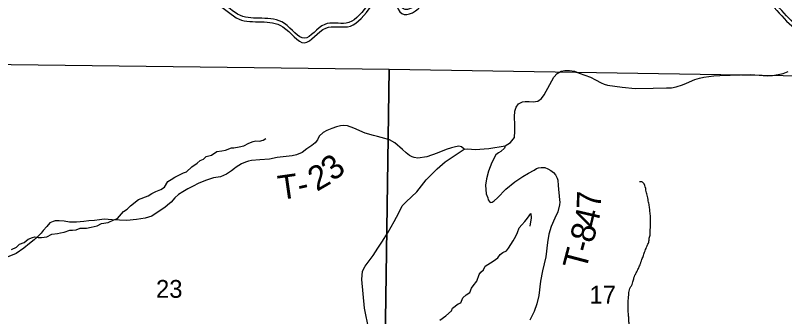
# Model space of a CAD drawing. Extents: x 0 to 191, y 0 to 55.
# Drawn here: x 147.556 to 148.459, y 21.192 to 21.545 of the extents above; entities that cross this region are included whole.
import ezdxf

# ---------------------------------------------------------------- set-up
doc = ezdxf.new("R2010")
doc.units = 0
for name, color, linetype in [('GM_X_Corporation', 7, 'Continuous'), ('GM_X_Minor_River', 7, 'Continuous'), ('GM_X_Section_Text', 7, 'Continuous'), ('GM_X_State_Route', 7, 'Continuous'), ('GM_X_Township_Road', 7, 'Continuous'), ('GM_X_Township_Road_Text', 7, 'Continuous')]:
    doc.layers.add(name, color=color, linetype=linetype)

msp = doc.modelspace()

# ---------------------------------------------------------------- linework, layer by layer
at = {"layer": 'GM_X_Corporation'}
for points in [[(147.48759, 21.48829), (147.99507, 21.48227), (147.98775, 20.97285), (147.48091, 20.97812)], [(147.99507, 21.48227), (148.5062, 21.47402), (148.49568, 20.96286), (147.98775, 20.97285)]]:
    msp.add_lwpolyline(points, close=True, dxfattribs=at)
at = {"layer": 'GM_X_Minor_River'}
for points in [[(147.55182, 21.27039), (147.55784, 21.27295), (147.56139, 21.27642), (147.56665, 21.27858), (147.57133, 21.28264), (147.57641, 21.28442), (147.57924, 21.28503), (147.58322, 21.28452), (147.58719, 21.28457), (147.59324, 21.28523), (147.59944, 21.28817), (147.60605, 21.28921), (147.60945, 21.28983), (147.61379, 21.29084), (147.62019, 21.29302), (147.62341, 21.29288), (147.62775, 21.29332), (147.63264, 21.29529), (147.64002, 21.29559), (147.64549, 21.29661), (147.65229, 21.29804), (147.65754, 21.30096), (147.66528, 21.30222), (147.67205, 21.30516), (147.67638, 21.30693), (147.68326, 21.31482), (147.68777, 21.31755), (147.69149, 21.32159), (147.70103, 21.32913), (147.71214, 21.33328), (147.71664, 21.33601), (147.72134, 21.33835), (147.72736, 21.34091), (147.73148, 21.34344), (147.73536, 21.35014), (147.7393, 21.35248), (147.7438, 21.3552), (147.75376, 21.36029), (147.75715, 21.36147), (147.76349, 21.36745), (147.76986, 21.37172), (147.77341, 21.37501), (147.77736, 21.37658), (147.78054, 21.37948), (147.78657, 21.38108), (147.79275, 21.38535), (147.79898, 21.38639), (147.80314, 21.38702), (147.8101, 21.38959), (147.81294, 21.38963), (147.81898, 21.39085), (147.82463, 21.39226), (147.83045, 21.39538), (147.83573, 21.39717), (147.83874, 21.39797), (147.8431, 21.39765), (147.84725, 21.39866), (147.85044, 21.40061)], [(148.05471, 21.18746), (148.06164, 21.19249), (148.06836, 21.19829), (148.06945, 21.20134), (148.07619, 21.20638), (148.07939, 21.20775), (148.08157, 21.21368), (148.0855, 21.21696), (148.08981, 21.21987), (148.092, 21.22503), (148.09386, 21.22772), (148.09794, 21.2331), (148.10105, 21.24093), (148.10271, 21.2438), (148.10588, 21.24651), (148.10809, 21.25091), (148.11728, 21.25674), (148.12271, 21.26062), (148.12549, 21.26446), (148.12867, 21.26697), (148.13299, 21.26893), (148.13541, 21.27182), (148.138, 21.27603), (148.14078, 21.28044), (148.14372, 21.28618), (148.14574, 21.29039), (148.14793, 21.29574), (148.15091, 21.29921), (148.15445, 21.30324), (148.15761, 21.30709), (148.15965, 21.30978), (148.1615, 21.31246), (148.16176, 21.30772), (148.16039, 21.29782)]]:
    msp.add_lwpolyline(points, dxfattribs=at)
for points in [[(147.57106, 21.67041), (147.59351, 21.65617), (147.61917, 21.64989), (147.64452, 21.63355), (147.66965, 21.62233), (147.69556, 21.60713), (147.72092, 21.58964), (147.74741, 21.57292), (147.77115, 21.59853), (147.76791, 21.57325), (147.79344, 21.55805), (147.81899, 21.54094), (147.84519, 21.5377), (147.87047, 21.5318), (147.89584, 21.51317), (147.92096, 21.53043), (147.94618, 21.53193), (147.97166, 21.55279), (147.99657, 21.5727), (148.01002, 21.54735), (148.03518, 21.5591), (148.05037, 21.58483), (148.07608, 21.59905), (148.10468, 21.60664), (148.13042, 21.61574), (148.15673, 21.62483), (148.18248, 21.63412), (148.20746, 21.64283), (148.23281, 21.65438), (148.25831, 21.64316), (148.28353, 21.6456), (148.30881, 21.63951), (148.33389, 21.63492), (148.35665, 21.60982), (148.38199, 21.59518), (148.40764, 21.59042), (148.43282, 21.57084), (148.45596, 21.5446), (148.48115, 21.52464), (148.50622, 21.52101), (148.5313, 21.51605), (148.55159, 21.49093), (148.57226, 21.46601), (148.59027, 21.44069), (148.61537, 21.43345), (148.64058, 21.40969), (148.66611, 21.39486), (148.69115, 21.39598), (148.71646, 21.38532), (148.73751, 21.36021), (148.76281, 21.35031), (148.78815, 21.33624), (148.81347, 21.3235), (148.8386, 21.31208), (148.86427, 21.30466), (148.89012, 21.29818), (148.91559, 21.29094), (148.94066, 21.28807), (148.96647, 21.28748), (148.99169, 21.28936), (149.01687, 21.29882), (149.04205, 21.30677), (149.06693, 21.31374)], [(147.57106, 21.67041), (147.59351, 21.65617), (147.61917, 21.64989), (147.64452, 21.63355), (147.66965, 21.62233), (147.69556, 21.60713), (147.72092, 21.58964), (147.74741, 21.57292), (147.77115, 21.59853), (147.76791, 21.57325), (147.79344, 21.55805), (147.81899, 21.54094), (147.84519, 21.5377), (147.87047, 21.5318), (147.89584, 21.51317), (147.92096, 21.53043), (147.94618, 21.53193), (147.97166, 21.55279), (147.99657, 21.5727), (148.01002, 21.54735), (148.03518, 21.5591), (148.05037, 21.58483), (148.07608, 21.59905), (148.10468, 21.60664), (148.13042, 21.61574), (148.15673, 21.62483), (148.18248, 21.63412), (148.20746, 21.64283), (148.23281, 21.65438), (148.25831, 21.64316), (148.28353, 21.6456), (148.30881, 21.63951), (148.33389, 21.63492), (148.35665, 21.60982), (148.38199, 21.59518), (148.40764, 21.59042), (148.43282, 21.57084), (148.45596, 21.5446), (148.48115, 21.52464), (148.50622, 21.52101), (148.5313, 21.51605), (148.55159, 21.49093), (148.57226, 21.46601), (148.59027, 21.44069), (148.61537, 21.43345), (148.64058, 21.40969), (148.66611, 21.39486), (148.69115, 21.39598), (148.71646, 21.38532), (148.73751, 21.36021), (148.76281, 21.35031), (148.78815, 21.33624), (148.81347, 21.3235), (148.8386, 21.31208), (148.86427, 21.30466), (148.89012, 21.29818), (148.91559, 21.29094), (148.94066, 21.28807), (148.96647, 21.28748), (148.99169, 21.28936), (149.01687, 21.29882), (149.04205, 21.30677), (149.06705, 21.31377)], [(149.05968, 21.31692), (149.04083, 21.31085), (149.01547, 21.30285), (148.99077, 21.29356), (148.96636, 21.29174), (148.94095, 21.29233), (148.91642, 21.29514), (148.89122, 21.3023), (148.86538, 21.30877), (148.84008, 21.31609), (148.81531, 21.32734), (148.79014, 21.34001), (148.76463, 21.35418), (148.74007, 21.36378), (148.71906, 21.38885), (148.69192, 21.40028), (148.66717, 21.39917), (148.64314, 21.41313), (148.61754, 21.43726), (148.59288, 21.44437), (148.57564, 21.46861), (148.55489, 21.49363), (148.53364, 21.51993), (148.50694, 21.52521), (148.48289, 21.52869), (148.45891, 21.5477), (148.43575, 21.57396), (148.40943, 21.59442), (148.38348, 21.59924), (148.35936, 21.61318), (148.33608, 21.63886), (148.3097, 21.64368), (148.28383, 21.64991), (148.25901, 21.64751), (148.23278, 21.65905), (148.20587, 21.64678), (148.18105, 21.63813), (148.15531, 21.62885), (148.12901, 21.61976), (148.10342, 21.61072), (148.07448, 21.60303), (148.04729, 21.588), (148.03218, 21.5624), (148.01189, 21.55293), (147.99792, 21.57924), (147.96898, 21.5561), (147.94455, 21.5361), (147.91952, 21.53461), (147.89592, 21.5184), (147.87229, 21.53575), (147.84594, 21.5419), (147.82052, 21.54505), (147.79572, 21.56165), (147.77249, 21.57548), (147.77706, 21.61118), (147.7467, 21.57842), (147.72327, 21.5932), (147.69785, 21.61072), (147.6716, 21.62612), (147.64656, 21.6373), (147.62088, 21.65386), (147.5952, 21.66014), (147.57469, 21.67316)], [(148.29508, 21.26731), (148.29732, 21.27302), (148.299, 21.27664), (148.29994, 21.27892), (148.30048, 21.28348), (148.30122, 21.28596), (148.30157, 21.29014), (148.30173, 21.29374), (148.30189, 21.29792), (148.30204, 21.30343), (148.30181, 21.31026), (148.30119, 21.31633), (148.30059, 21.32183), (148.29941, 21.32752), (148.29803, 21.33435), (148.29726, 21.33681), (148.29666, 21.34022), (148.29434, 21.34742), (148.29166, 21.34987), (148.2892, 21.34967)], [(148.24976, 20.86339), (148.25479, 20.86869), (148.25667, 20.87098), (148.25873, 20.87537), (148.26286, 20.88128), (148.26512, 20.88395), (148.26757, 20.8872), (148.2685, 20.88948), (148.27057, 20.89215), (148.27281, 20.89635), (148.27469, 20.89997), (148.27751, 20.90359), (148.27919, 20.90683), (148.2839, 20.91256), (148.2888, 20.91677), (148.29201, 20.91964), (148.29539, 20.92365), (148.29973, 20.92824), (148.30329, 20.93396), (148.30648, 20.9393), (148.30835, 20.9433), (148.31021, 20.94862), (148.31152, 20.9511), (148.31207, 20.95338), (148.31319, 20.95738), (148.31393, 20.95985), (148.31597, 20.96556), (148.31709, 20.96899), (148.31838, 20.97374), (148.3193, 20.97774), (148.31986, 20.98002), (148.31984, 20.98249), (148.3202, 20.98553), (148.32056, 20.98819), (148.32129, 20.99218), (148.32203, 20.99484), (148.32258, 20.99731), (148.3235, 21.00131), (148.32443, 21.00511), (148.32574, 21.0074), (148.32591, 21.00987), (148.32551, 21.0129), (148.32473, 21.01651), (148.32279, 21.02276), (148.32105, 21.02712), (148.31798, 21.03127), (148.31644, 21.03525), (148.31432, 21.03998), (148.31238, 21.04529), (148.30987, 21.05153), (148.30775, 21.05684), (148.30562, 21.06309), (148.30386, 21.0701), (148.30153, 21.07749), (148.29998, 21.08185), (148.29883, 21.08431), (148.29651, 21.08942), (148.29574, 21.09207), (148.29457, 21.09643), (148.29321, 21.10022), (148.29205, 21.10325), (148.2907, 21.10723), (148.28914, 21.11253), (148.28875, 21.115), (148.28758, 21.11898), (148.28622, 21.12315), (148.28562, 21.1277), (148.28483, 21.13206), (148.28424, 21.13547), (148.28365, 21.13813), (148.28227, 21.14552), (148.28149, 21.14856), (148.2803, 21.15614), (148.27971, 21.15937), (148.27852, 21.16676), (148.27812, 21.16961), (148.27732, 21.17606), (148.27711, 21.17834), (148.27688, 21.18327), (148.27668, 21.18555), (148.27666, 21.18783), (148.27625, 21.192), (148.27611, 21.21288), (148.27628, 21.21535), (148.27663, 21.21972), (148.27848, 21.226), (148.28055, 21.22943), (148.28129, 21.23247), (148.28258, 21.23704), (148.2837, 21.24008), (148.28576, 21.24409), (148.28726, 21.24694), (148.28913, 21.25113), (148.29025, 21.2538), (148.29136, 21.25722), (148.29341, 21.26217), (148.29508, 21.26731)]]:
    msp.add_spline(points, degree=3, dxfattribs=at)
at = {"layer": 'GM_X_State_Route'}
msp.add_lwpolyline([(147.97118, 21.17648), (147.96645, 21.20164), (147.9631, 21.2352), (147.96401, 21.2448), (147.96691, 21.2509), (147.97636, 21.26326), (147.98201, 21.2718), (147.98658, 21.27881), (147.99404, 21.29058), (148.00107, 21.30342), (148.00661, 21.3133), (148.01067, 21.32163), (148.01499, 21.32623), (148.02756, 21.33819), (148.03863, 21.35212), (148.05164, 21.36515), (148.06083, 21.37327), (148.08335, 21.38837), (148.08766, 21.38859), (148.09612, 21.38796), (148.11215, 21.38915), (148.13147, 21.392), (148.13771, 21.39601), (148.1422, 21.40198), (148.14272, 21.40933), (148.14265, 21.41656), (148.14238, 21.42628), (148.14287, 21.43288), (148.14413, 21.43767), (148.14684, 21.44131), (148.15173, 21.44358), (148.15484, 21.44411), (148.15946, 21.44405), (148.1644, 21.44368), (148.16956, 21.44437), (148.17391, 21.44754), (148.17706, 21.45212), (148.18372, 21.464), (148.18853, 21.47262), (148.19227, 21.47708), (148.19717, 21.47959), (148.20149, 21.48041), (148.20672, 21.48068), (148.21295, 21.47982), (148.21828, 21.47761), (148.23153, 21.47262), (148.23737, 21.46977), (148.2442, 21.46607), (148.24766, 21.46465), (148.25133, 21.4634), (148.26867, 21.46087), (148.28414, 21.45953), (148.30502, 21.45999), (148.32094, 21.46004), (148.32661, 21.46018), (148.33209, 21.46121), (148.33956, 21.46369), (148.34433, 21.46583), (148.35403, 21.47011), (148.35956, 21.47159), (148.36452, 21.47262), (148.37636, 21.47413), (148.38326, 21.47465), (148.41978, 21.47579), (148.4389, 21.47445), (148.44523, 21.47461), (148.4519, 21.47579), (148.45775, 21.47702), (148.46352, 21.47935)], dxfattribs=at)
at = {"layer": 'GM_X_Township_Road'}
for points in [[(148.08335, 21.38837), (148.08016, 21.39082), (148.07705, 21.39159), (148.07304, 21.39108), (148.06828, 21.38983), (148.06213, 21.38777), (148.05152, 21.38354), (148.0396, 21.37905), (148.0288, 21.37771), (148.02466, 21.37842), (148.02207, 21.37917), (148.01902, 21.38072), (148.01502, 21.38369), (148.01086, 21.3877), (148.00181, 21.39579), (147.99572, 21.39927), (147.99001, 21.40077), (147.98145, 21.40312), (147.9767, 21.40441), (147.96703, 21.407), (147.95355, 21.41298), (147.94647, 21.41541), (147.94198, 21.41587), (147.9381, 21.41541), (147.93353, 21.41438), (147.92805, 21.41257), (147.92215, 21.41028), (147.91781, 21.40772), (147.9132, 21.40337), (147.91104, 21.39931), (147.90845, 21.39581), (147.90447, 21.39238), (147.89863, 21.38858), (147.89322, 21.38439), (147.8866, 21.38165), (147.88119, 21.38043), (147.87419, 21.3796), (147.86369, 21.37846), (147.85494, 21.37661), (147.84336, 21.37583), (147.83366, 21.37469), (147.83023, 21.37404), (147.82646, 21.37305), (147.82174, 21.371), (147.81883, 21.36898), (147.81573, 21.36723), (147.81356, 21.36529), (147.81006, 21.36278), (147.80419, 21.35883), (147.79708, 21.35588), (147.78912, 21.35448), (147.78098, 21.35166), (147.77161, 21.34808), (147.76446, 21.34443), (147.75871, 21.34147), (147.75319, 21.33819), (147.74794, 21.33484), (147.74345, 21.33088), (147.73918, 21.32585), (147.735, 21.32235), (147.73172, 21.31961), (147.72647, 21.31603), (147.71658, 21.30964), (147.70886, 21.30707), (147.69874, 21.30547), (147.68743, 21.30441), (147.66994, 21.30505), (147.66067, 21.30579), (147.65512, 21.30537), (147.64936, 21.30441), (147.64265, 21.30398), (147.63679, 21.30313), (147.62815, 21.30259), (147.62004, 21.30259), (147.61365, 21.30345), (147.60799, 21.30387), (147.6032, 21.30387), (147.60085, 21.30334), (147.59701, 21.30163), (147.59349, 21.29748), (147.58923, 21.29278), (147.58678, 21.28958), (147.58262, 21.28532), (147.57846, 21.28159), (147.57302, 21.27743), (147.56641, 21.2721), (147.55735, 21.26559), (147.54698, 21.26123)], [(148.13147, 21.392), (148.13047, 21.38941), (148.12643, 21.38532), (148.12354, 21.38384), (148.12046, 21.38135), (148.11571, 21.37244), (148.11171, 21.3623), (148.10941, 21.35332), (148.10839, 21.34608), (148.10915, 21.33584), (148.11094, 21.33112), (148.11155, 21.32885), (148.11254, 21.32697), (148.11389, 21.32566), (148.11597, 21.32588), (148.11842, 21.32745), (148.12235, 21.33094), (148.13223, 21.34119), (148.14272, 21.34974), (148.1521, 21.35618), (148.15868, 21.3601), (148.16527, 21.36345), (148.16827, 21.3654), (148.17035, 21.3662), (148.17357, 21.36683), (148.17775, 21.36653), (148.18158, 21.36507), (148.18503, 21.36305), (148.1883, 21.36082), (148.19063, 21.3582), (148.19241, 21.35425), (148.19303, 21.3516), (148.19352, 21.34533), (148.19496, 21.32883), (148.19558, 21.3258), (148.19506, 21.32275), (148.19331, 21.31455), (148.18984, 21.30707), (148.18545, 21.2973), (148.18276, 21.28832), (148.18123, 21.27841), (148.17924, 21.26185), (148.17536, 21.24543), (148.17292, 21.23304), (148.17094, 21.21628), (148.16865, 21.20635), (148.16538, 21.19755), (148.16025, 21.18739)]]:
    msp.add_lwpolyline(points, dxfattribs=at)

# ---------------------------------------------------------------- texts
at = {"layer": 'GM_X_Section_Text'}
for s, p in [('23', (147.7215, 21.21362)), ('17', (148.23025, 21.2068))]:
    msp.add_text(s, height=0.020928, rotation=0.00001, dxfattribs=at).set_placement(p)
at = {"layer": 'GM_X_Township_Road_Text'}
for s, rotation, p in [('3', 39.26605, (147.92957, 21.34959)), ('2', 30.05046, (147.91033, 21.338)), ('T', 8.08828, (147.86678, 21.3285)), ('-', 13.16367, (147.89052, 21.33199)), ('7', 89.18208, (148.24377, 21.31807)), ('4', 76.88434, (148.23899, 21.29444)), ('8', 75.55702, (148.23445, 21.27679)), ('T', 75.28086, (148.22606, 21.24481)), ('-', 75.32982, (148.23147, 21.26539))]:
    msp.add_text(s, height=0.02841, rotation=rotation, dxfattribs=at).set_placement(p)

doc.saveas('drawing.dxf')
